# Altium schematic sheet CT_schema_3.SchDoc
size 469 x 363 mm
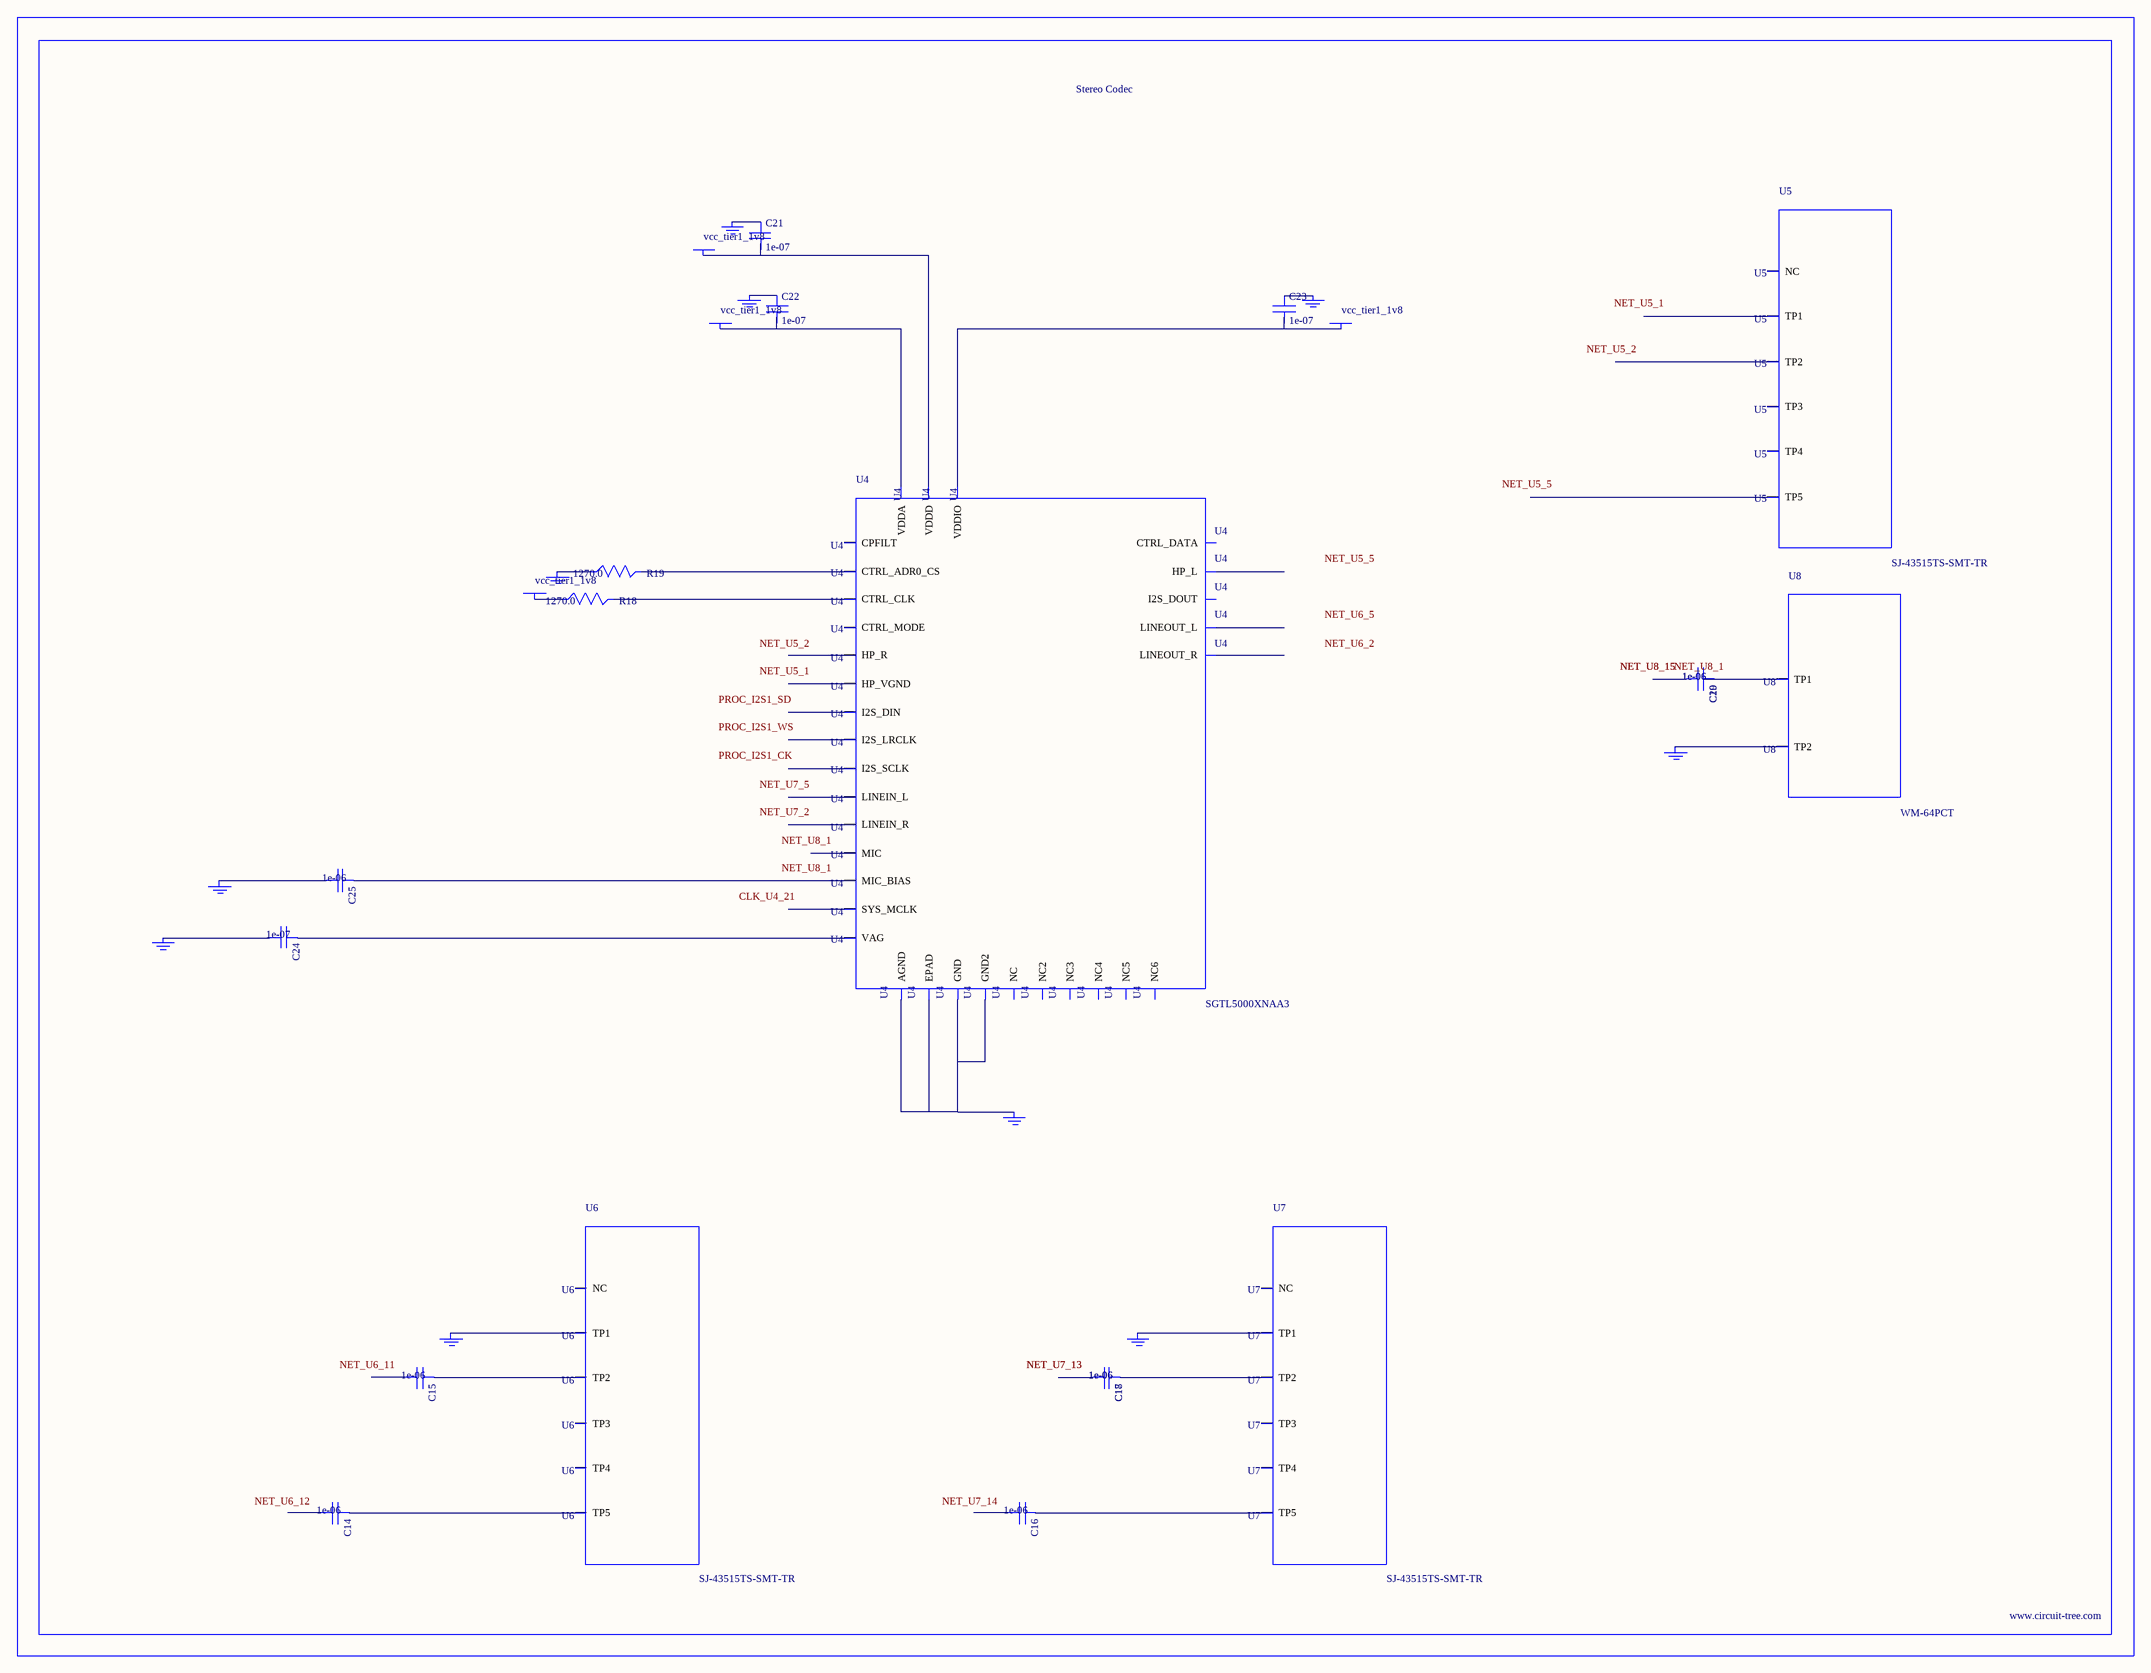
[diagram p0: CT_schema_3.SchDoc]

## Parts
BORDER2  (no value)
C14  1e-06  [C0603]
C15  1e-06  [C0603]
C16  1e-06  [C0603]
C17  1e-06  [C0603]
C18  1e-06  [C0603]
C19  1e-06  [C0603]
C20  1e-06  [C0603]
C21  1e-07  [C0402]
C22  1e-07  [C0402]
C23  1e-07  [C0402]
C24  1e-07  [C0402]
C25  1e-06  [C0603]
GND_INSTANCE_2_0  (no value)
GND_INSTANCE_2_1  (no value)
GND_INSTANCE_2_2  (no value)
GND_INSTANCE_2_3  (no value)
GND_INSTANCE_2_4  (no value)
GND_INSTANCE_2_5  (no value)
GND_INSTANCE_2_6  (no value)
GND_INSTANCE_2_7  (no value)
GND_INSTANCE_2_8  (no value)
GND_INSTANCE_2_9  (no value)
GND_INSTANCE_2_10  (no value)
POWER_INSTANCE_2_0  vcc_tier1_1v8
POWER_INSTANCE_2_1  vcc_tier1_1v8
POWER_INSTANCE_2_2  vcc_tier1_1v8
POWER_INSTANCE_2_3  vcc_tier1_1v8
R18  1270.0  [R0603]
R19  1270.0  [R0603]
U4  SGTL5000XNAA3  [QFN-32]
U5  SJ-43515TS-SMT-TR  [SJ-43515TS-SMT-TR]
U6  SJ-43515TS-SMT-TR  [SJ-43515TS-SMT-TR]
U7  SJ-43515TS-SMT-TR  [SJ-43515TS-SMT-TR]
U8  WM-64PCT  [WM-64PC]

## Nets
NetC14_1: C14.1 U6.5(TP5)
NetC15_1: C15.1 U6.2(TP2)
NetC16_1: C16.1 U7.5(TP5)
NetC17_1: C17.1 C18.1 U7.2(TP2)
NetC17_2: C17.2 C18.2
NetC19_1: C19.1 C20.1 U8.1(TP1)
NetC19_2: C19.2 C20.2
NetC21_1: C21.1 GND_INSTANCE_2_5.0(GND)
NetC21_2: C21.2 POWER_INSTANCE_2_3.0(PWR) U4.30(VDDD)
NetC22_1: C22.1 GND_INSTANCE_2_1.0(GND)
NetC22_2: C22.2 POWER_INSTANCE_2_0.0(PWR) U4.5(VDDA)
NetC23_1: C23.1 GND_INSTANCE_2_4.0(GND)
NetC23_2: C23.2 POWER_INSTANCE_2_1.0(PWR) U4.20(VDDIO)
NetC24_1: C24.1 U4.10(VAG)
NetC24_2: C24.2 GND_INSTANCE_2_2.0(GND)
NetC25_1: C25.1 U4.16(MIC_BIAS)
NetC25_2: C25.2 GND_INSTANCE_2_3.0(GND)
NetGND_INSTANCE_2_0_0: GND_INSTANCE_2_0.0(GND) U4.1(GND) U4.3(GND2) U4.7(AGND) U4.EXP(EPAD)
NetGND_INSTANCE_2_6_0: GND_INSTANCE_2_6.0(GND) R19.1
NetGND_INSTANCE_2_7_0: GND_INSTANCE_2_7.0(GND) U6.1(TP1)
NetGND_INSTANCE_2_8_0: GND_INSTANCE_2_8.0(GND) GND_INSTANCE_2_9.0(GND) U7.1(TP1)
NetGND_INSTANCE_2_10_0: GND_INSTANCE_2_10.0(GND) U8.2(TP2)
NetPOWER_INSTANCE_2_2_0: POWER_INSTANCE_2_2.0(PWR) R18.1
NetR18_2: R18.2 U4.29(CTRL_CLK)
NetR19_2: R19.2 U4.31(CTRL_ADR0_CS)

Not connected (* = marked no-connect by the designer): C14 2; C15 2; C16 2; U4 2(HP_R) 4(HP_VGND) 6(HP_L) 8(NC) 9(NC2) 11(LINEOUT_R) 12(LINEOUT_L) 13(LINEIN_R) 14(LINEIN_L) 15(MIC) 17(NC3) 18(CPFILT) 19(NC4) 21(SYS_MCLK) 22(NC5) 23(I2S_LRCLK) 24(I2S_SCLK) 25(I2S_DOUT) 26(I2S_DIN) 27(CTRL_DATA) 28(NC6) 32(CTRL_MODE); U5 1(TP1) 2(TP2) 3(TP3) 4(TP4) 5(TP5) 6(NC); U6 3(TP3) 4(TP4) 6(NC); U7 3(TP3) 4(TP4) 6(NC)

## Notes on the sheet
- Labels drawn without touching a wire or pin: CLK_U4_21, NET_U5_1, NET_U5_2, NET_U5_5, NET_U6_2, NET_U6_5, NET_U6_11, NET_U6_12, NET_U7_2, NET_U7_5, NET_U7_14, NET_U8_1, PROC_I2S1_CK, PROC_I2S1_SD, PROC_I2S1_WS

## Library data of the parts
BORDER2 = BORDER_PAGE2
C14-C20 C25 = C0603C105K3RACTU
C21-C24 = C0402C104K3RACTU
GND_INSTANCE_2_0-GND_INSTANCE_2_10 = GND
POWER_INSTANCE_2_0-POWER_INSTANCE_2_3 = PWR
R18 R19 = RC0603FR-071K27L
